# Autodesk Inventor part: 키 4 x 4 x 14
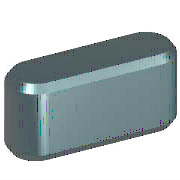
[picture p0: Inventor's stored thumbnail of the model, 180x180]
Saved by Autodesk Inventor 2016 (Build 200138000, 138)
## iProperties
Created: 2012-02
Part Number: 키 4 x 4 x 14
Material: 강철, 연강
Description: 키 및 해당 키홈
Document SubType Name: Modeling
Standard: KS B 1311
Designer: test
Standards Organization: KS
Language: ko-KR
Size Designation: 4 x 4 x 14
Categories: <MemberInstance><Categories><Category DisplayName="샤프트 부품" InternalName="7f7aeb1f-a693-4053-b835-cee3144e0d98" Mnemonic="SHFT"><Category DisplayName="키" Interna
Density: 1 g/cm^3
Appearance: 노란색
IsCustomPart: 1
Author: test
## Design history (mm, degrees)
workplane "Work Plane1"
workplane "Work Plane2"
sketch "스케치1"
  geometry: L1 (2, 2)-(12, 2); L2 (12, -2)-(2, -2); L3 (0, 9.4)-(0, -7.4) reference; L4 (-5, 0)-(30, 0) reference; L5 (14, 0)-(14, 7); A1 r 2 centre (2, 0) between (2, 2) and (2, -2); A2 r 2 centre (12, 0) between (12, -2) and (12, 2)
  constraints: 6 end point, 5 point on circle, 4 tangent, 3 point on line, 2 centre point, 1 horizontal, 1 parallel, 1 perpendicular
  dimensions: "d0" = 2 radius of A1 (= 0.5 x PB); "d13" = 2 radius of A2 (= 0.5 x PB); "d14" = 14 distance between parallel lines of L5 L3 (= NLG)
extrude "본체1" new body sketch "스케치1" taper "d3" = 0 deg; stored distance "d4" = 10
workplane "Work Plane3"
body "Solid1"
chamfer "모따기1" distance "d8" = 0.25 (= PHH); stored, may be unused: second distance "d9" = 0.25 (= PHH), angle "d15" = 45 deg
other parameters: "d1" = -2.5 (= -PNT), "d2" = 1.5 (= PH - PNT), "NLG" = 14 [user parameter; used in 3 equation terms], "PB" = 4 [user parameter; used in 2 equation terms], "PNT" = 2.5 [user parameter; used in 2 equation terms], "PH" = 4 [user parameter; used in 1 equation term], "PHH" = 0.25 [user parameter; used in 2 equation terms], "d10" = 0, "d16" = 0, "d17" = 0, "d18" = 0, "PLB2" = 14 (= NLG) [user parameter], "WDMAX" = 12 [user parameter], "PLB1" = 14 (= NLG) [user parameter], "RR" = 0.08 [user parameter], "PUEB" = 1.8 [user parameter]
